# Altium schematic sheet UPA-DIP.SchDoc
size 139 x 101 mm; DocumentNumber: 1; SheetNumber: 1; SheetTotal: 1; PageSetup: Record=PageOptions¦CenterHorizontal=True¦CenterVertical=True¦PrintScale=0.05¦XCorrection=1.00¦YCorrection=1.00¦PrintKind=0¦BorderSize=5000000¦LeftOffset=0¦BottomOffset=0¦Orientation=2¦PaperLength=1000¦PaperWidth=1000¦Scale=100¦PaperSource=7¦PrintQuality=-3¦MediaType=1¦DitherType=10¦PrintScaleMode=1¦PaperKind=12mm¦PaperIndex=126
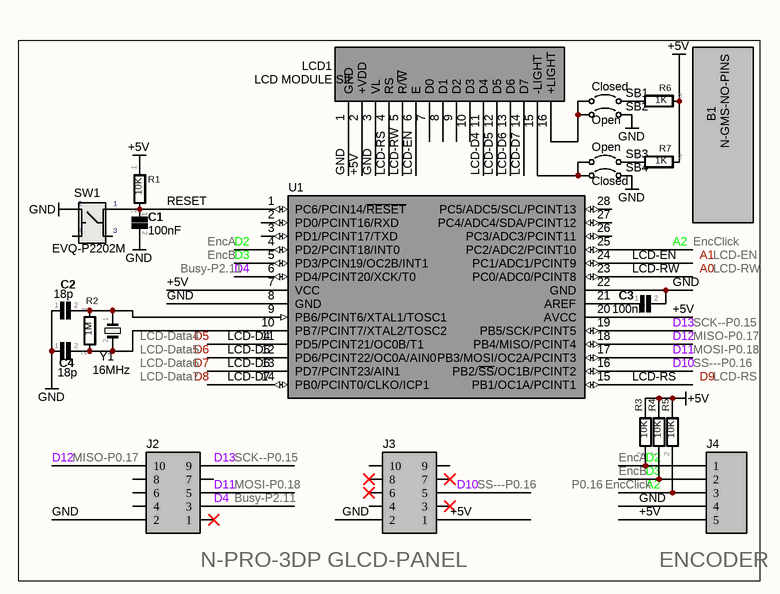
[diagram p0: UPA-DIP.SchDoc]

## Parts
B1  N-GMS-NO-PINS  [N-GMS-NO-PINS]
C1  100nF  [CK05]
C2  18p  [CK05]
C3  100nF  [CK05]
C4  18p  [CK05]
J2  Header 5X2  [ML10]  (value not drawn)
J3  Header 5X2  [ML10]  (value not drawn)
J4  HEADER_5  [1X05]  (value not drawn)
LCD1  LCD MODULE SIL  [1X16-FEMALE]
R1  10K  [RS-2,5]
R2  1M  [RS-2,5]
R3  10K  [RS-2,5]
R4  10K  [RS-2,5]
R5  10K  [RS-2,5]
R6  1Κ  [RS-2,5]
R7  1Κ  [RS-2,5]
SB1  Closed  [0603_JUMPER]
SB2  Open  [0603_JUMPER]
SB3  Open  [0603_JUMPER]
SB4  Closed  [0603_JUMPER]
SW1  EVQ-P2202M  [BUTTON_6X6mm]
U1  ATmega328PU  [DIL28-300wSOCKET]  (value not drawn)
Y1  16MHz  [HC49U-V]

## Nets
+5V: J3.1 J4.5 LCD1.2(+VDD) R1.1 R3.1 R4.1 R5.1 R6.2 R7.2 U1.7(VCC) U1.20(AVCC)
GND: C1.2 C2.1 C3.2 C4.1 J2.2 J3.2 J4.4 LCD1.1(GND) LCD1.3(VL) SB2.2 SB4.2 SW1.2 U1.8(GND) U1.22(GND)
A2: J4.3 R5.2 U1.25(PC2/ADC2/PCINT10)
D2: J4.1 R3.2 U1.4(PD2/PCINT18/INT0)
D3: J4.2 R4.2 U1.5(PD3/PCIN19/OC2B/INT1)
D4: J2.3 U1.6(PD4/PCINT20/XCK/T0)
D10: J3.5 U1.16(PB2/~{SS}/OC1B/PCINT2)
D11: J2.5 U1.17(PB3/MOSI/OC2A/PCINT3)
D12: J2.10 U1.18(PB4/MISO/PCINT4)
D13: J2.9 U1.19(PB5/SCK/PCINT5)
LCD-D4: LCD1.11(D4) U1.11(PD5/PCINT21/OC0B/T1)
LCD-D5: LCD1.12(D5) U1.12(PD6/PCINT22/OC0A/AIN0)
LCD-D6: LCD1.13(D6) U1.13(PD7/PCINT23/AIN1)
LCD-D7: LCD1.14(D7) U1.14(PB0/PCINT0/CLKO/ICP1)
LCD-EN: LCD1.6(E) U1.24(PC1/ADC1/PCINT9)
LCD-RS: LCD1.4(RS) U1.15(PB1/OC1A/PCINT1)
LCD-RW: LCD1.5(R/~{W}) U1.23(PC0/ADC0/PCINT8)
RESET: C1.1 R1.2 SW1.1 U1.1(PC6/PCIN14/~{RESET})
NetC2_2: C2.2 R2.1 U1.9(PB6/PCINT6/XTAL1/TOSC1) Y1.1
NetC3_1: C3.1 U1.21(AREF)
NetC4_2: C4.2 R2.2 U1.10(PB7/PCINT7/XTAL2/TOSC2) Y1.2
NetLCD1_15: LCD1.15(-LIGHT) SB3.1 SB4.1
NetLCD1_16: LCD1.16(+LIGHT) SB1.1 SB2.1
NetR6_1: R6.1 SB1.2
NetR7_1: R7.1 SB3.2

Not connected (* = marked no-connect by the designer): J2 1* 4 6 7 8; J3 3* 4 6* 7* 8* 9 10; LCD1 7(D0) 8(D1) 9(D2) 10(D3); SW1 3 4; U1 2(PD0/PCINT16/RXD) 3(PD1/PCINT17/TXD) 26(PC3/ADC3/PCINT11) 27(PC4/ADC4/SDA/PCINT12) 28(PC5/ADC5/SCL/PCINT13)

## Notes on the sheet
- EncA
- EncB
- EncClick
- LCD-EN
- (near Y1) LCD-Data4
- Busy-P2.11
- (near C3) SCK--P0.15
- MISO-P0.17
- LCD-RW
- (near Y1) LCD-Data5
- LCD-Data6
- LCD-Data7
- MOSI-P0.18
- SS---P0.16
- LCD-RS
- (near J2) MISO-P0.17
- (near J2) SCK--P0.15
- (near R3) EncA
- (near J2) MOSI-P0.18
- (near J2) Busy-P2.11
- (near J3) SS---P0.16
- P0.16
- N-PRO-3DP GLCD-PANEL
- (near J4) ENCODER
- Labels drawn without touching a wire or pin: A0, A1, D5, D6, D7, D8, D9

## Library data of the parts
C1-C4 = C: CAPACITOR; Divider: 1
J2 J3 = Header 5X2: Header, 5-Pin, Dual row; Divider: 1
LCD1 = LCD MODULE SIL_1: LCD MODULE SINGLE IN LINE
R1-R7 = R: RESISTOR; Divider: 1
SB1-SB4 = HEADER2_CIRCUIT_BRAKER: Circuit Breaker; Solder: NO
SW1 = BUTTON_TACT: BUTTON TACTILE; Divider: 1
U1 = ATmega48/88/168: 8-Bit AVR Microcontroller with 32K Bytes of In-System Programmable Flash Memory
Y1 = XTAL: CRYSTAL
